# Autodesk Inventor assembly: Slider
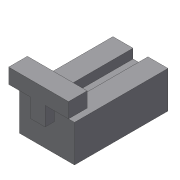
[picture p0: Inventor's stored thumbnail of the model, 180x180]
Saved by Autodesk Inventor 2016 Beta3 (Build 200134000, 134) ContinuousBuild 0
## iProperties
Created: 2016-03
Part Number: Slider
Document SubType Name: Assembly
Designer: Gaurav
Author: Gaurav
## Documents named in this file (3)
- D:\My Data\Books_Final Books\Autodesk Inventor 2015_resources\Chapter 7\Slider\Slider.iam
- D:\My Data\Books_Final Books\Autodesk Inventor 2015_resources\Chapter 7\Slider\Base.ipt
- D:\My Data\Books_Final Books\Autodesk Inventor 2015_resources\Chapter 7\Slider\slider.ipt
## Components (2 placed, 2 different names)
1. Base:1 — Mate:1, Slider:1
2. slider:1 — Slider:1
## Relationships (2: Mate 1, TranslationJoint 1)
- Mate:1: Base:1
- Slider:1 [TranslationJoint]: Base:1 ↔ slider:1
